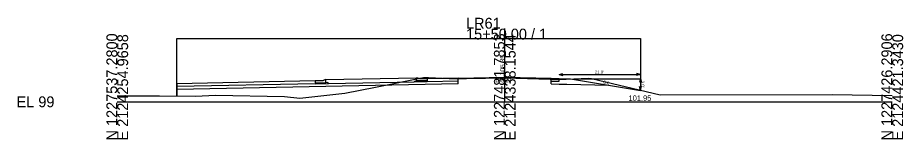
# Model space of a CAD drawing. Extents: x 2126751 to 2128979, y 1225108 to 1234639.
# Drawn here: x 2127750.9 to 2127979.4, y 1230607.5 to 1230639 of the extents above; entities that cross this region are included whole.
import ezdxf

# ---------------------------------------------------------------- set-up
doc = ezdxf.new("R2010")
doc.units = 0
for name, color, linetype in [('XS_CELL', 7, 'Continuous'), ('XS_M_DITCH', 7, 'Continuous'), ('XS_P_CURB_GUTTER', 7, 'Continuous'), ('XS_P_FINISHED_GRADE', 7, 'Continuous'), ('XS_P_FINISHED_GRADE_ELEV_TX', 7, 'Continuous'), ('XS_P_SUBGRADE_GRANULAR', 7, 'Continuous'), ('XS_P_SUBGRADE_GRANULAR_B', 7, 'Continuous'), ('XS_P_SUBGRADE_LEVELING', 7, 'Continuous'), ('XS_P_SUBGRADE_PAVEMENT', 7, 'Continuous'), ('XS_P_TX_CLEARZONE', 7, 'Continuous'), ('XS_P_TX_DCH', 7, 'Continuous'), ('XS_P_TX_FS_BS', 7, 'Continuous'), ('XS_X_GROUND', 7, 'Continuous'), ('XS_X_GROUND_TX', 7, 'Continuous')]:
    doc.layers.add(name, color=color, linetype=linetype)

msp = doc.modelspace()

# ---------------------------------------------------------------- linework, layer by layer
at = {"layer": 'XS_CELL'}
for p, q in [((2127876.61, 1230617.21), (2127876.61, 1230636.12)), ((2127776.61, 1230617.21), (2127876.61, 1230617.21)), ((2127876.61, 1230617.21), (2127976.61, 1230617.21))]:
    msp.add_line(p, q, dxfattribs=at)
at = {"layer": 'XS_M_DITCH'}
for p, q in [((2127792.01, 1230618.72), (2127792.01, 1230633.56)), ((2127792.01, 1230633.56), (2127911.61, 1230633.56)), ((2127911.61, 1230633.56), (2127911.61, 1230620.16))]:
    msp.add_line(p, q, dxfattribs=at)
at = {"layer": 'XS_P_CURB_GUTTER'}
for p, q in [((2127830.45, 1230622.16), (2127830.45, 1230622.97)), ((2127853.86, 1230622.6), (2127853.86, 1230623.44)), ((2127856.61, 1230623.16), (2127856.61, 1230622.66)), ((2127827.7, 1230622.61), (2127827.7, 1230622.11)), ((2127827.7, 1230622.11), (2127830.45, 1230622.16)), ((2127856.61, 1230622.66), (2127853.86, 1230622.6))]:
    msp.add_line(p, q, dxfattribs=at)
at = {"layer": 'XS_P_FINISHED_GRADE'}
for p, q in [((2127830.45, 1230622.97), (2127829.7, 1230622.73)), ((2127830.45, 1230622.97), (2127853.86, 1230623.44)), ((2127854.61, 1230623.2), (2127853.86, 1230623.44)), ((2127854.61, 1230623.12), (2127854.61, 1230623.2)), ((2127856.61, 1230623.16), (2127854.61, 1230623.12)), ((2127864.61, 1230623.32), (2127856.61, 1230623.16)), ((2127864.61, 1230623.32), (2127876.61, 1230623.56)), ((2127876.61, 1230623.56), (2127888.61, 1230623.32)), ((2127888.61, 1230623.32), (2127890.61, 1230623.28)), ((2127890.61, 1230623.28), (2127893.61, 1230623.16)), ((2127893.61, 1230623.16), (2127911.61, 1230620.16)), ((2127827.7, 1230622.61), (2127792.01, 1230621.89)), ((2127792.01, 1230621.89), (2127792.01, 1230618.72)), ((2127829.7, 1230622.65), (2127827.7, 1230622.61)), ((2127829.7, 1230622.73), (2127829.7, 1230622.65)), ((2127911.61, 1230620.16), (2127911.76, 1230620.21))]:
    msp.add_line(p, q, dxfattribs=at)
at = {"layer": 'XS_P_SUBGRADE_GRANULAR'}
for p, q in [((2127864.61, 1230621.82), (2127792.01, 1230620.36)), ((2127864.61, 1230621.82), (2127864.61, 1230622.57)), ((2127888.61, 1230621.82), (2127888.61, 1230622.57)), ((2127888.61, 1230621.82), (2127890.61, 1230621.78)), ((2127890.61, 1230621.78), (2127892.61, 1230621.74)), ((2127892.61, 1230621.74), (2127903.43, 1230621.52))]:
    msp.add_line(p, q, dxfattribs=at)
at = {"layer": 'XS_P_SUBGRADE_GRANULAR_B'}
for p, q in [((2127830.45, 1230622.15), (2127830.45, 1230622.97)), ((2127853.86, 1230622.6), (2127853.86, 1230623.44)), ((2127830.95, 1230622.16), (2127830.45, 1230622.15)), ((2127831.1, 1230621.93), (2127830.95, 1230622.16)), ((2127831.1, 1230621.93), (2127853.21, 1230622.34)), ((2127853.21, 1230622.34), (2127853.36, 1230622.59)), ((2127853.36, 1230622.59), (2127853.86, 1230622.6))]:
    msp.add_line(p, q, dxfattribs=at)
at = {"layer": 'XS_P_SUBGRADE_LEVELING'}
for p, q in [((2127864.61, 1230623.32), (2127864.61, 1230623.24)), ((2127864.61, 1230623.24), (2127866.73, 1230623.28)), ((2127866.73, 1230623.28), (2127876.53, 1230623.43)), ((2127876.53, 1230623.43), (2127888.35, 1230623.05)), ((2127888.35, 1230623.05), (2127888.61, 1230623.04)), ((2127888.61, 1230623.32), (2127888.61, 1230623.04))]:
    msp.add_line(p, q, dxfattribs=at)
at = {"layer": 'XS_P_SUBGRADE_PAVEMENT'}
for p, q in [((2127864.61, 1230622.57), (2127864.61, 1230623.24)), ((2127888.61, 1230622.57), (2127888.61, 1230623.04)), ((2127890.61, 1230622.53), (2127890.61, 1230623.28)), ((2127827.7, 1230621.86), (2127792.01, 1230621.14)), ((2127827.7, 1230621.86), (2127830.95, 1230621.92)), ((2127830.95, 1230621.92), (2127831.1, 1230621.93)), ((2127853.36, 1230622.34), (2127853.21, 1230622.34)), ((2127856.61, 1230622.41), (2127853.36, 1230622.34)), ((2127864.61, 1230622.57), (2127856.61, 1230622.41)), ((2127888.61, 1230622.57), (2127890.61, 1230622.53))]:
    msp.add_line(p, q, dxfattribs=at)
at = {"layer": 'XS_P_TX_CLEARZONE'}
for p, q in [((2127890.61, 1230624.28), (2127891.61, 1230624.53)), ((2127890.61, 1230624.28), (2127891.61, 1230624.03)), ((2127890.61, 1230624.28), (2127911.61, 1230624.28)), ((2127894.61, 1230623.16), (2127911.61, 1230623.16)), ((2127911.61, 1230624.28), (2127910.61, 1230624.53)), ((2127911.61, 1230624.28), (2127910.61, 1230624.03)), ((2127911.61, 1230623.16), (2127911.36, 1230622.16)), ((2127911.61, 1230623.16), (2127911.61, 1230620.16)), ((2127911.61, 1230623.16), (2127911.86, 1230622.16)), ((2127911.61, 1230620.16), (2127911.36, 1230621.16)), ((2127911.61, 1230620.16), (2127911.86, 1230621.16))]:
    msp.add_line(p, q, dxfattribs=at)
at = {"layer": 'XS_X_GROUND'}
for p, q in [((2127843.27, 1230620.96), (2127855.66, 1230623.51)), ((2127855.66, 1230623.51), (2127856.94, 1230623.46)), ((2127856.94, 1230623.46), (2127862.27, 1230623.2)), ((2127862.27, 1230623.2), (2127866.73, 1230623.28)), ((2127866.73, 1230623.28), (2127876.53, 1230623.43)), ((2127876.53, 1230623.43), (2127888.35, 1230623.05)), ((2127888.35, 1230623.05), (2127890.57, 1230622.99)), ((2127890.57, 1230622.99), (2127898.24, 1230623.31)), ((2127898.24, 1230623.31), (2127899.01, 1230623.2)), ((2127899.01, 1230623.2), (2127916.71, 1230619.05)), ((2127835.36, 1230619.48), (2127843.27, 1230620.96)), ((2127776.61, 1230618.73), (2127787.47, 1230618.75)), ((2127787.47, 1230618.75), (2127796.83, 1230618.69)), ((2127796.83, 1230618.69), (2127801.94, 1230618.9)), ((2127801.94, 1230618.9), (2127819.73, 1230618.58)), ((2127819.73, 1230618.58), (2127823.69, 1230618.16)), ((2127823.69, 1230618.16), (2127835.36, 1230619.48)), ((2127916.71, 1230619.05), (2127961.06, 1230619.08)), ((2127961.06, 1230619.08), (2127976.61, 1230618.85))]:
    msp.add_line(p, q, dxfattribs=at)

# ---------------------------------------------------------------- texts
at = {"layer": 'XS_CELL'}
for s, p in [('LR61', (2127866.61, 1230636.12)), ('15+50.00 / 1', (2127866.61, 1230633.32)), ('EL 99', (2127750.61, 1230615.81))]:
    msp.add_text(s, height=2.8, dxfattribs=at).set_placement(p)
for s, p in [('N 1227537.2800', (2127776.61, 1230607.21)), ('E 2124254.9658', (2127779.41, 1230607.21)), ('N 1227481.7853', (2127876.61, 1230607.21)), ('E 2124338.1544', (2127879.41, 1230607.21)), ('N 1227426.2906', (2127976.61, 1230607.21)), ('E 2124421.3430', (2127979.41, 1230607.21))]:
    msp.add_text(s, height=2.8, rotation=90, dxfattribs=at).set_placement(p)
at = {"layer": 'XS_P_FINISHED_GRADE_ELEV_TX'}
msp.add_text(' 105.35', height=1.25, rotation=90, dxfattribs=at).set_placement((2127876.61, 1230623.56))
at = {"layer": 'XS_P_TX_CLEARZONE'}
msp.add_text("21.0'", height=0.8, dxfattribs=at).set_placement((2127899.82, 1230624.48))
msp.add_text("3.0'", height=0.8, rotation=270, dxfattribs=at).set_placement((2127911.81, 1230622.68))
at = {"layer": 'XS_P_TX_DCH'}
msp.add_text('101.95', height=1.4, dxfattribs=at).set_placement((2127908.54, 1230617.46))
at = {"layer": 'XS_P_TX_FS_BS'}
msp.add_text('6:1', height=0.8, rotation=350.5377, dxfattribs=at).set_placement((2127901.95, 1230621.97))
at = {"layer": 'XS_X_GROUND_TX'}
msp.add_text('105.22', height=1, dxfattribs=at).set_placement((2127874.05, 1230622.27))

doc.saveas('drawing.dxf')
